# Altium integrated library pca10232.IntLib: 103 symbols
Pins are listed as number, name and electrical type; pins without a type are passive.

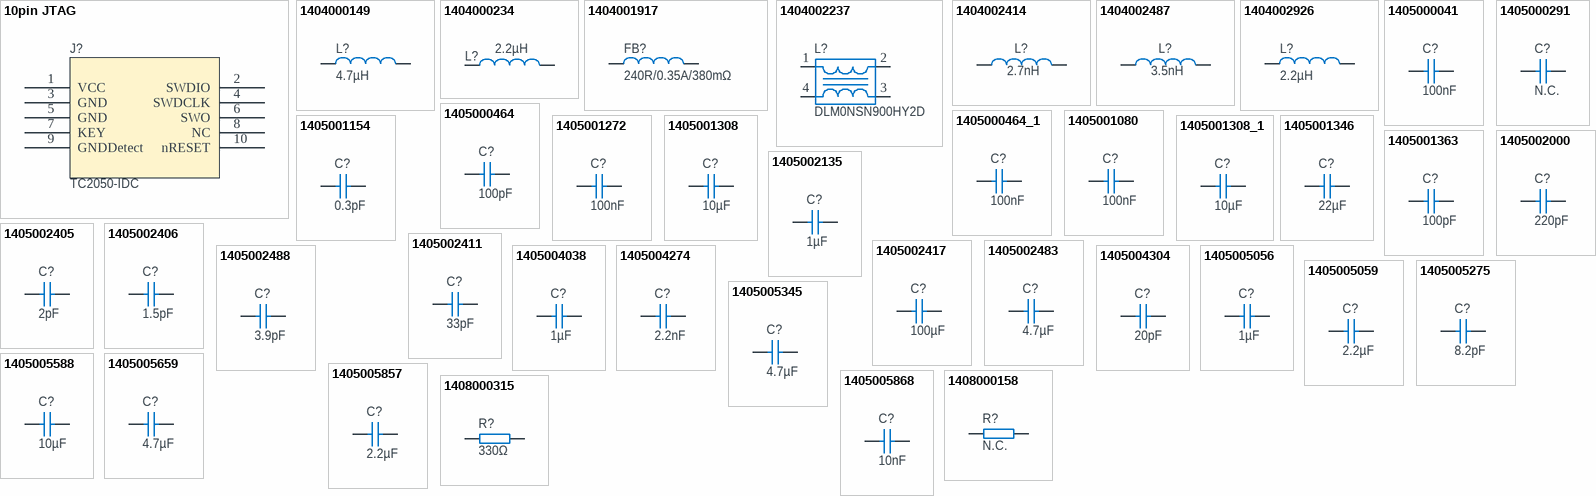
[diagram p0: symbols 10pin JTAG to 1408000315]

## 10pin JTAG
designator J?, comment TC2050-IDC
footprint TC2050-IDC-NLFP
pins: 1 VCC, 2 SWDIO, 3 GND, 4 SWDCLK, 5 GND, 6 SWO, 7 KEY, 8 NC, 9 GNDDetect, 10 nRESET

## 1404000149
designator L?, comment 4.7µH
0603
footprint 0603L_0.6D
footprint 0603C_0.6D(RF)
pins: 1, 2

## 1404000234
designator L?, comment 2.2µH
2.2uH/20%/2.5*2*1.2/2.07A/0.166Ω; Manufacturer Part Number: SWPA252012S2R2MT; Manufacturer: Sunlord
footprint SKFB160808-2R2M
pins: 1, 2

## 1404001917
designator FB?, comment 240R/0.35A/380mΩ
Manufacturer: Murata
footprint 0201_0.25D
footprint 0201L_0.2D(NB)
pins: 1, 2

## 1404002237
designator L?, comment DLM0NSN900HY2D
90Ω/0.1A/3.8Ω; Manufacturer Part Number: DLM0NSM900HY2#; Manufacturer: Murata
footprint L-0.85X0.65
pins: 1 (oe), 2 (oe), 3 (oe), 4 (oe)

## 1404002414
designator L?, comment 2.7nH
2.7nH/±0.1nH/500mA/0.2Ω; Manufacturer Part Number: SDCL0603Q2N7BT02B03; Manufacturer: Sunlord
footprint 0201_0.25D
pins: 1, 2

## 1404002487
designator L?, comment 3.5nH
3.4nH/±0.1nH/450mA/0.25Ω; Manufacturer Part Number: SDCL0603Q3N4BT02B03; Manufacturer: Sunlord
footprint 0201_0.25D
pins: 1, 2

## 1404002926
designator L?, comment 2.2µH
2.2uH/20%/2.0*1.2*0.8/1.7A/146mΩ; Manufacturer Part Number: SKFB201208PA2R2M; Manufacturer: Scientic
footprint 0805L_0.7D-NB
pins: 1, 2

## 1405000041
designator C?, comment 100nF
0.1uF/16V/10%/X7R; Manufacturer Part Number: CC0402KRX7R7BB104; Manufacturer: Yageo
footprint 0402C_0.4D
footprint 0201
footprint 000
footprint 888
pins: 1, 2

## 1405000291
designator C?, comment N.C.
33pF/50V/5%/C0G; Manufacturer Part Number: CC0402JRNPO9BN330; Manufacturer: Yageo
footprint 0402C_0.4D
pins: 1, 2

## 1405000464
designator C?, comment 100pF
100pF/16V/10%/X7R; Manufacturer Part Number: CL05B104KO5NNNC; Manufacturer: Samsung
footprint 0402C_0.4D
pins: 1, 2

## 1405000464_1
designator C?, comment 100nF
0.1uF/16V/10%/X7R; Manufacturer Part Number: CL05B104KO5NNNC; Manufacturer: Samsung
footprint 0402C_0.4D
pins: 1, 2

## 1405001080
designator C?, comment 100nF
0.1uF/10V/10%/X5R; Manufacturer Part Number: 0201X104K100CT; Manufacturer: Walsin
footprint 0201_0.25D
pins: 1, 2

## 1405001154
designator C?, comment 0.3pF
0.3pF/50V/±0.1pF/GQC; Manufacturer Part Number: V0R3B0201GQC500NAT; Manufacturer: Viiyong
footprint 0201_0.25D
pins: 1, 2

## 1405001272
designator C?, comment 100nF
0.1uF/10V/10%/X5R; Manufacturer Part Number: V104K0201X5R100NAT; Manufacturer: Viiyong
footprint 0201_0.25D
pins: 1, 2

## 1405001308
designator C?, comment 10µF
10uF/10V/20%/X5R; Manufacturer Part Number: CL05A106MP5NUNC; Manufacturer: Samsung
footprint 0402C_0.4D
pins: 1, 2

## 1405001308_1
designator C?, comment 10µF
10uF/10V/20%/X5R; Manufacturer Part Number: CL05A106MP5NUNC; Manufacturer: Samsung
footprint 0402C_0.4D
footprint 0402C_0.4D-NB
pins: 1, 2

## 1405001346
designator C?, comment 22µF
22uF/10V/20%/X5R; Manufacturer Part Number: CL10A226MP8NUN#; Manufacturer: Samsung
footprint 0603C_0.6D
pins: 1, 2

## 1405001363
designator C?, comment 100pF
100pF/50V/5%/C0G; Manufacturer Part Number: V101J0201C0G500NAT; Manufacturer: Viiyong
footprint 0201_0.25D
pins: 1, 2

## 1405002000
designator C?, comment 220pF
8pF/50V/0.1pF/C0G; Manufacturer Part Number: GRM0335C1H8R0BA01D; Manufacturer: Murata
footprint 0201_0.25D
footprint 0201C_0.2D(NB)
pins: 1, 2

## 1405002135
designator C?, comment 1µF
1uF/25V/10%/X5R; Manufacturer Part Number: CL05A105KA5NQNC; Manufacturer: Samsung
footprint 0402C_0.4D
pins: 1, 2

## 1405002405
designator C?, comment 2pF
2pF/50V/±0.1pF/GQC; Manufacturer Part Number: V2R0B0201GQC500NAT; Manufacturer: Viiyong
footprint 0201_0.25D
pins: 1, 2

## 1405002406
designator C?, comment 1.5pF
1.5pF/50V/±0.1pF/GQC; Manufacturer Part Number: V1R5B0201GQC500NAT; Manufacturer: Viiyong
footprint 0201_0.25D
pins: 1, 2

## 1405002411
designator C?, comment 33pF
33pF/50V/5%/C0G; Manufacturer Part Number: V330J0201C0G500NAT; Manufacturer: Viiyong
footprint 0201_0.25D
pins: 1, 2

## 1405002417
designator C?, comment 100µF
100uF/6.3V/20%/X5R; Manufacturer Part Number: CL31A107MQHNNNE; Manufacturer: Samsung
footprint 1206C_1.2D
pins: 1, 2

## 1405002483
designator C?, comment 4.7µF
4.7uF/16V/20%/X5R; Manufacturer Part Number: CL05A475MO5NUNC; Manufacturer: Samsung
footprint 0402C_0.4D
pins: 1, 2

## 1405002488
designator C?, comment 3.9pF
3.9pF/50V/±0.1pF/C0G; Manufacturer Part Number: V3R9B0201C0G500NAT; Manufacturer: Viiyong
footprint 0201_0.25D
pins: 1, 2

## 1405004038
designator C?, comment 1µF
1uF/16V/10%/X5R; Manufacturer Part Number: CL05A105KO5NNNC; Manufacturer: Samsung
footprint 0402C_0.4D
pins: 1, 2

## 1405004274
designator C?, comment 2.2nF
2.2nF/16V/10%/X7R; Manufacturer Part Number: CC0201KRX7R7BB222; Manufacturer: Yageo
footprint 0201_0.25D
pins: 1, 2

## 1405004304
designator C?, comment 20pF
20pF/50V/5%/C0G; Manufacturer Part Number: V200J0201C0G500NAT; Manufacturer: Viiyong
footprint 0201_0.25D
pins: 1, 2

## 1405005056
designator C?, comment 1µF
1uF/10V/20%/X5R; Manufacturer Part Number: V105M0201X5R100NXT; Manufacturer: Viiyong
footprint 0201_0.25D
pins: 1, 2

## 1405005059
designator C?, comment 2.2µF
2.2uF/10V/20%/X5R; Manufacturer Part Number: V225M0201X5R100NXT; Manufacturer: Viiyong
footprint 0201_0.25D
pins: 1, 2

## 1405005275
designator C?, comment 8.2pF
8.2pF/50V/±0.1pF/C0G; Manufacturer Part Number: CC0201BRNPO9BN8R2; Manufacturer: Yageo
footprint 0201_0.25D
pins: 1, 2

## 1405005345
designator C?, comment 4.7µF
4.7uF/6.3V/20%/X5R; Manufacturer Part Number: CL03A475MQ5C65C; Manufacturer: Samsung
footprint 0201_0.25D
pins: 1, 2

## 1405005588
designator C?, comment 10µF
10uF/25V/20%/X5R; Manufacturer Part Number: CC0603MRX5R8BB106; Manufacturer: Yageo
footprint 0603C_0.6D
pins: 1, 2

## 1405005659
designator C?, comment 4.7µF
4.7uF/10V/10%/X5R; Manufacturer Part Number: V475K0402X5R100NCT; Manufacturer: Viiyong
footprint 0402C_0.4D
pins: 1, 2

## 1405005857
designator C?, comment 2.2µF
2.2uF/16V/10%/X5R; Manufacturer Part Number: V225K0402X5R160NNT; Manufacturer: Viiyong
footprint 0402C_0.4D
pins: 1, 2

## 1405005868
designator C?, comment 10nF
10nF/25V/10%/X7R; Manufacturer Part Number: V103K0201X7R250NAT; Manufacturer: Viiyong
footprint 0201_0.25D
pins: 1, 2

## 1408000158
designator R?, comment N.C.
10K/5%; Manufacturer Part Number: RC0402JR-0710KL; Manufacturer: Yageo
footprint 0402R_0.4D
pins: 1, 2

## 1408000315
designator R?, comment 330Ω
330Ω/5%; Manufacturer Part Number: 0402WGJ0331TCE; Manufacturer: Uniohm
footprint 0402R_0.4D
pins: 1, 2

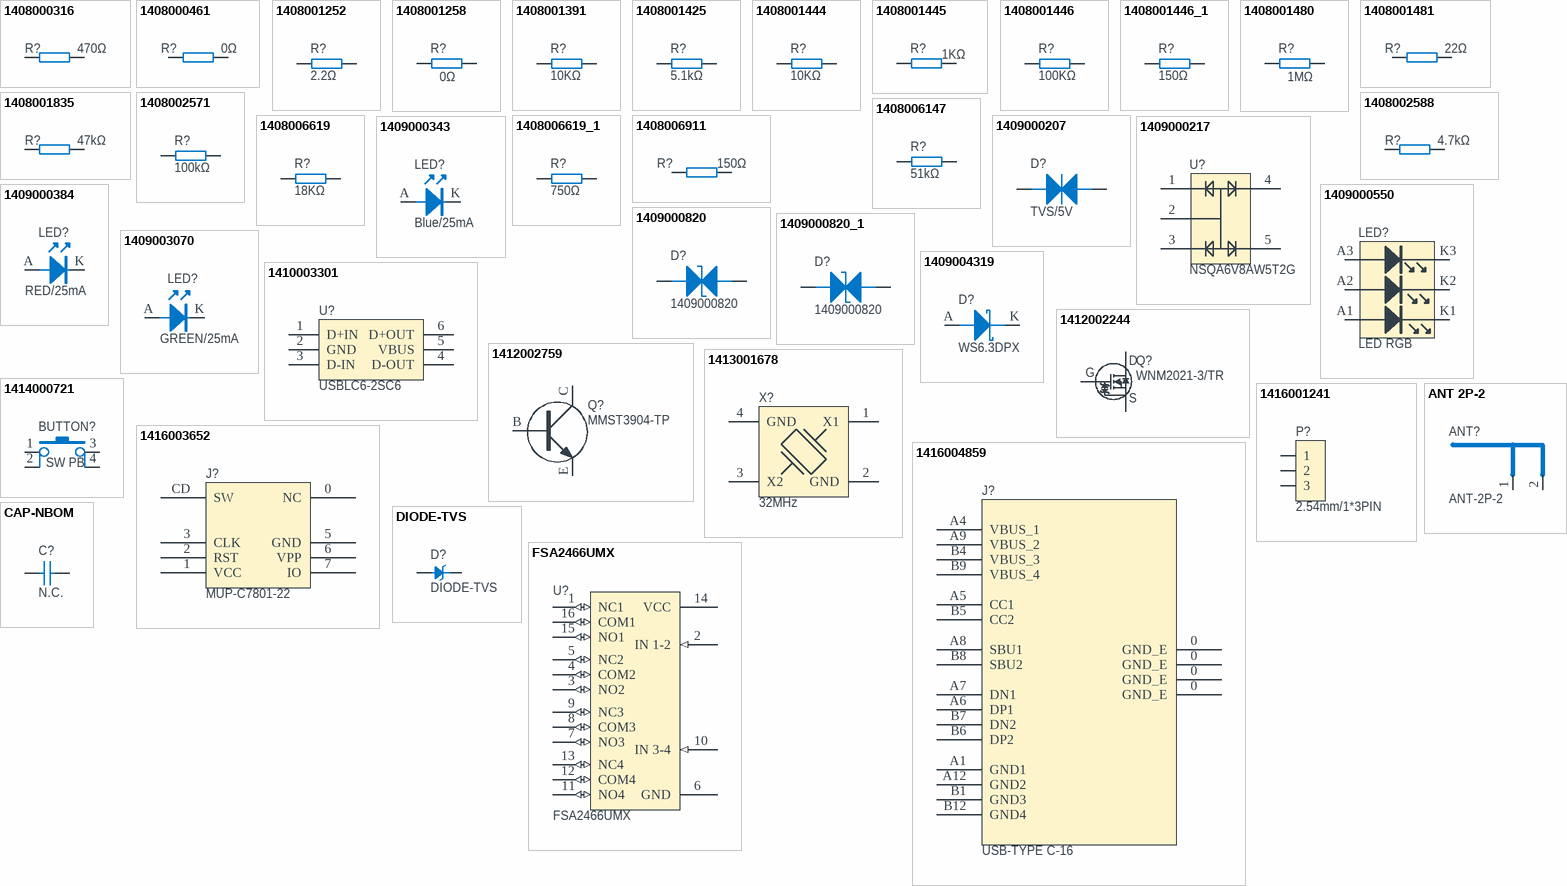
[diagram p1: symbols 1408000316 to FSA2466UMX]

## 1408000316
designator R?, comment 470Ω
470Ω/5%; Manufacturer Part Number: RC0402JR-07470RL; Manufacturer: Yageo
footprint 0402R_0.4D
pins: 1, 2

## 1408000461
designator R?, comment 0Ω
0Ω/5%; Manufacturer Part Number: RC0402JR-070RL; Manufacturer: Yageo
footprint 0402R_0.4D
pins: 1, 2

## 1408001252
designator R?, comment 2.2Ω
2.2Ω/1%; Manufacturer Part Number: 0402WGF220KTCE; Manufacturer: Uniohm
footprint 0402R_0.4D
pins: 1, 2

## 1408001258
designator R?, comment 0Ω
0Ω/1%; Manufacturer Part Number: RC0402FR-070RL; Manufacturer: Yageo
footprint 0402R_0.4D
pins: 1, 2

## 1408001391
designator R?, comment 10KΩ
10KΩ/1%; Manufacturer Part Number: RC0201FR-0710KL; Manufacturer: Yageo
footprint 0201_0.25D
pins: 1, 2

## 1408001425
designator R?, comment 5.1kΩ
5.1KΩ/1%; Manufacturer Part Number: RC0201FR-075K1L; Manufacturer: Yageo
footprint 0201_0.25D
pins: 1, 2

## 1408001444
designator R?, comment 10KΩ
10KΩ/5%; Manufacturer Part Number: RC0201JR-0710KL; Manufacturer: Yageo
footprint 0201_0.25D
pins: 1, 2

## 1408001445
designator R?, comment 1KΩ
1KΩ/5%; Manufacturer Part Number: RC0201JR-071KL; Manufacturer: Yageo
footprint 0201_0.25D
pins: 1, 2

## 1408001446
designator R?, comment 100KΩ
100KΩ/5%; Manufacturer Part Number: RC0201JR-07100KL; Manufacturer: Yageo
footprint 0201_0.25D
pins: 1, 2

## 1408001446_1
designator R?, comment 150Ω
150Ω/5%; Manufacturer: Yageo
footprint 0201_0.25D
pins: 1, 2

## 1408001480
designator R?, comment 1MΩ
1MΩ/1%; Manufacturer Part Number: RC0201FR-071ML; Manufacturer: Yageo
footprint 0201_0.25D
pins: 1, 2

## 1408001481
designator R?, comment 22Ω
22Ω/1%; Manufacturer Part Number: RC0201FR-0722RL; Manufacturer: Yageo
footprint 0201_0.25D
pins: 1, 2

## 1408001835
designator R?, comment 47kΩ
47KΩ/1%; Manufacturer Part Number: RC0201FR-0747KL; Manufacturer: Yageo
footprint 0201_0.25D
pins: 1, 2

## 1408002571
designator R?, comment 100kΩ
100KΩ/1%; Manufacturer Part Number: 0201WMF1003TEE; Manufacturer: Uniohm
footprint 0201_0.25D
pins: 1, 2

## 1408002588
designator R?, comment 4.7kΩ
4.7KΩ/1%; Manufacturer Part Number: 0201WMF4701TEE; Manufacturer: Uniohm
footprint 0201_0.25D
pins: 1, 2

## 1408006147
designator R?, comment 51kΩ
51K/5%; Manufacturer Part Number: RJ0201-51K; Manufacturer: Uniohm
footprint 0201_0.25D
pins: 1, 2

## 1408006619
designator R?, comment 18KΩ
18KΩ/1%; Manufacturer Part Number: RC0201FR-0718KL; Manufacturer: Yageo
footprint 0201_0.25D
pins: 1, 2

## 1408006619_1
designator R?, comment 750Ω
750Ω/1%; Manufacturer: Yageo
footprint 0201_0.25D
pins: 1, 2

## 1408006911
designator R?, comment 150Ω
150Ω/1%; Manufacturer Part Number: RC0201FR-07150RL; Manufacturer: Yageo
footprint 0201_0.25D
pins: 1, 2

## 1409000207
designator D?, comment TVS/5V
ESD; Manufacturer: Nexperia
footprint SOD-523-NP
pins: A, K

## 1409000217
designator U?, comment NSQA6V8AW5T2G
7.14V/600W; Manufacturer: Onsemi
footprint SOT-323-5
pins: 1, 2, 3, 4, 5

## 1409000343
designator LED?, comment Blue/25mA
25mA/28.5-72mcd; Manufacturer Part Number: 16-213/BHC-AN1P2/3T; Manufacturer: Everlight
footprint D0402
pins: A, K

## 1409000384
designator LED?, comment RED/25mA
25mA/40mcd; Manufacturer Part Number: 16-213SURC/S530-A3/TR8; Manufacturer: Everlight
footprint D0402
pins: A, K

## 1409000550
designator LED?, comment LED RGB
25mA/100mcd,180mcd, 50mcd; Manufacturer Part Number: 19-337/R6GHBHC-A01/2T; Manufacturer: Everlight
footprint D1616-RGB
pins: A1 A, A2 A, A3 A, K1 K, K2 K, K3 K

## 1409000820
designator D?
5V/100W
footprint D0201-NP
pins: A, K

## 1409000820_1
designator D?, comment 1409000820
5V/100W
footprint DFN1006
pins: A, K

## 1409003070
designator LED?, comment GREEN/25mA
25mA/112-225mcd; Manufacturer Part Number: 16-213/GHC-YR1S1N/3T; Manufacturer: Everlight
footprint D0402
pins: A, K

## 1409004319
designator D?, comment WS6.3DPX
Manufacturer: Walsin
footprint UDFN2(1610)
pins: A, K

## 1410003301
designator U?, comment USBLC6-2SC6
USB; Manufacturer: ST
footprint SOT-23-6P
pins: 1 D+IN, 2 GND, 3 D-IN, 4 D-OUT, 5 VBUS, 6 D+OUT

## 1412002244
designator Q?, comment WNM2021-3/TR
NMOS/20V/0.89A; Manufacturer: Willsemi
footprint SOT-323-3G
pins: D, G, S

## 1412002759
designator Q?, comment MMST3904-TP
NPN/200mA/40V/200mW; Manufacturer: MCC
footprint SOT-323-3A
pins: B 1, C 3, E 2

## 1413001678
designator X?, comment 32MHz
8pF/32MHz/10PPM/-40~85℃; Manufacturer Part Number: 9S32000073
footprint 2016
pins: 1 X1, 2 GND, 3 X2, 4 GND

## 1414000721
designator BUTTON?, comment SW PB
3.2*4.2*2.5mm; Manufacturer Part Number: BL-QC-3.2X4.2
footprint SW-4.2X3.35-4P-S
pins: 1, 2, 3, 4

## 1416001241
designator P?, comment 2.54mm/1*3PIN
Manufacturer Part Number: CNT-M254-1*3-GS-6/3-01
footprint SIP 2.54_3_S
pins: 1, 2, 3

## 1416003652
designator J?, comment MUP-C7801-22
NANO SIM; Manufacturer: MUP
footprint SIM-MUP-C7801
pins: 0 NC, 1 VCC, 2 RST, 3 CLK, 5 GND, 6 VPP, 7 IO, CD SW

## 1416004859
designator J?, comment USB-TYPE C-16
USB2.0 TpyeC; Manufacturer Part Number: MUP-U20402-01; Manufacturer: MUP
footprint USB-TYPEC-MUP-U20402-1
pins: 0 GND_E, 0 GND_E, 0 GND_E, 0 GND_E, A1 GND1, A4 VBUS_1, A5 CC1, A6 DP1, A7 DN1, A8 SBU1, A9 VBUS_2, A12 GND2, B1 GND3, B4 VBUS_3, B5 CC2, B6 DP2, B7 DN2, B8 SBU2, B9 VBUS_4, B12 GND4

## ANT 2P-2
designator ANT?, comment ANT-2P-2  (no BOM)
ANT
footprint ANT_PCB
pins: 1 "-1", 2 "-1"

## CAP-NBOM
designator C?, comment N.C.
Manufacturer Part Number: N.A.
footprint 0402C_0.4D
footprint 0603C_0.6D
footprint 0805C_0.6D
footprint 0201_0.25D
footprint 1206C_1.2D
footprint CY-L7W3P5
footprint CY-L9W3_5P7_5
footprint CY-L10W3_5P8
footprint CY-L11W5P7_5
footprint CY-L15W3_5P10
footprint CX-L10_5W4P7_5
footprint CX-L10_5W5P7_5
footprint CX-L10_5W6P7_5
footprint CX-L13W4P10
footprint CX-L13W5P10
footprint CX-L13W6P10
footprint CX-L13W7P10
footprint CX-L13W8P10
footprint CX-L17_5W5P15
footprint CX-L17_5W6P15
footprint CX-L17_5W10P15
footprint CX-L17.5W8P15
footprint CX-L26_5W6P22_5
footprint 01005_0.16D
pins: 1, 2

## DIODE-TVS
designator D?
4.5V; Manufacturer Part Number: WS4.5DPVL; Manufacturer: Walsin
footprint UDFN2(1610) (Footprint not found)
footprint UDFN2(1610)
pins: A, K

## FSA2466UMX
designator U?
Data / Audio Low-Voltage Dual DPDT Analog Switch; Manufacturer: Onsemi
footprint FSA2466UMX_1.8x2.6_0.4
pins: 1 NC1 (io), 2 IN 1-2 (in), 3 NO2 (io), 4 COM2 (io), 5 NC2 (io), 6 GND (power), 7 NO3 (io), 8 COM3 (io), 9 NC3 (io), 10 IN 3-4 (in), 11 NO4 (io), 12 COM4 (io), 13 NC4 (io), 14 VCC (power), 15 NO1 (io), 16 COM1 (io)
1 alternate drawing of the same symbol

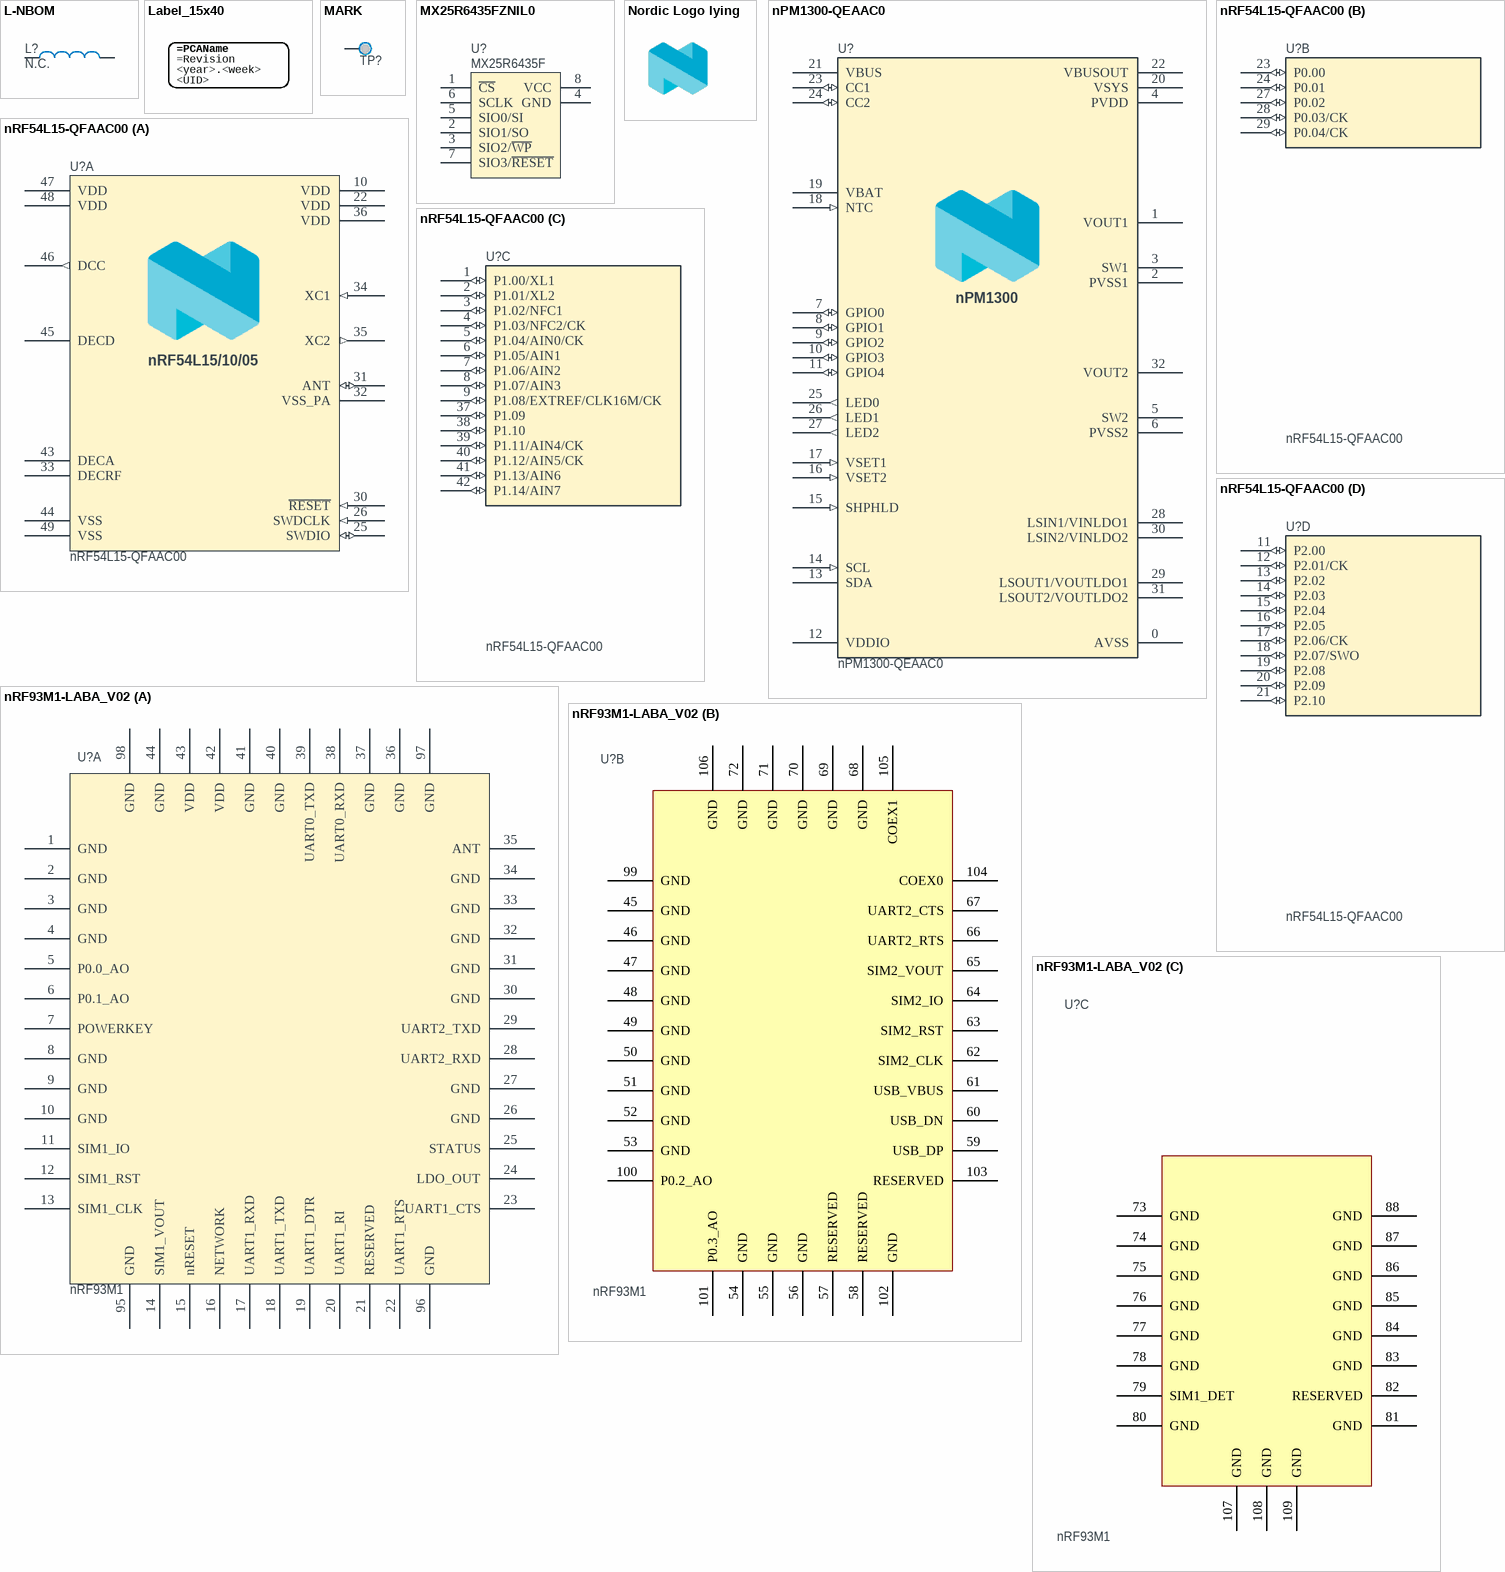
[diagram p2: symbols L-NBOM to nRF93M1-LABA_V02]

## L-NBOM
designator L?, comment N.C.
Manufacturer Part Number: N.A.
footprint 0201_0.25D
footprint 0402L_0.4D
footprint 0603L_0.6D
footprint 0805L_0.6D
footprint 2520-L
footprint 1206L_1.8D
footprint 3X3-L
footprint 4X4-L
footprint 5X5-L
footprint 6X6-L
footprint 8X8-L
footprint 01005_0.16D
pins: 1, 2

## Label_15x40
designator LABEL?, comment Solderbridge  (value not drawn)  (graphical)
PCA version label, stick-on, 15x40mm
footprint LabelSilk_15x40

## MARK
designator TP?, comment Testpoint  (value not drawn)  (no BOM)
Manufacturer Part Number: N.A.
footprint test
footprint Bad Mark
pins: 1

## MX25R6435FZNIL0
designator U?, comment MX25R6435F
Ultra low power, 64M-bit, serial multi I/O flash memory; Manufacturer: Macronix
footprint WSON8L_6X5_1.27
pins: 1 ~{CS}, 2 SIO1/SO, 3 SIO2/~{WP}, 4 GND, 5 SIO0/SI, 6 SCLK, 7 SIO3/~{RESET}, 8 VCC, 9 GND hidden to GND

## Nordic Logo lying
designator LOGO?, comment Solderbridge  (value not drawn)  (graphical)
Nordic logo lying
footprint NORDIC_LOGO_LYING

## nPM1300-QEAAC0
designator U?
Li-Ion/Li-Polymer USB-C battery charger with high efficiency buck regulators, LDOs or load switches, LED drivers, TWI and VBUSOUT; Manufacturer: Nordic Semiconductor
footprint QFN32(0.5)-5X5
pins: 0 AVSS (power), 1 VOUT1 (power), 2 PVSS1 (power), 3 SW1 (power), 4 PVDD (power), 5 SW2 (power), 6 PVSS2 (power), 7 GPIO0 (io), 8 GPIO1 (io), 9 GPIO2 (io), 10 GPIO3 (io), 11 GPIO4 (io), 12 VDDIO (power), 13 SDA (oc), 14 SCL (in), 15 SHPHLD (in), 16 VSET2 (in), 17 VSET1 (in), 18 NTC (in), 19 VBAT, 20 VSYS (power), 21 VBUS (power), 22 VBUSOUT (power), 23 CC1 (io), 24 CC2 (io), 25 LED0 (out), 26 LED1 (out), 27 LED2 (out), 28 LSIN1/VINLDO1 (power), 29 LSOUT1/VOUTLDO1 (power), 30 LSIN2/VINLDO2 (power), 31 LSOUT2/VOUTLDO2 (power), 32 VOUT2 (power)

## nRF54L15-QFAAC00
designator U?
Multi-protocol Bluetooth Low Energy, IEEE 802.15.4 and 2.4GHz proprietary Wireless MCU; Manufacturer: Nordic Semiconductor
footprint nRF54L15_QFN48_6X6_0.4
part A pins: 10 VDD (power), 22 VDD (power), 25 SWDIO (io), 26 SWDCLK (in), 30 ~{RESET} (in), 31 ANT (io), 32 VSS_PA (power), 33 DECRF (power), 34 XC1 (in), 35 XC2 (out), 36 VDD (power), 43 DECA (power), 44 VSS (power), 45 DECD (power), 46 DCC (out), 47 VDD (power), 48 VDD (power), 49 VSS (power)
part B pins: 23 P0.00 (io), 24 P0.01 (io), 27 P0.02 (io), 28 P0.03/CK (io), 29 P0.04/CK (io)
part C pins: 1 P1.00/XL1 (io), 2 P1.01/XL2 (io), 3 P1.02/NFC1 (io), 4 P1.03/NFC2/CK (io), 5 P1.04/AIN0/CK (io), 6 P1.05/AIN1 (io), 7 P1.06/AIN2 (io), 8 P1.07/AIN3 (io), 9 P1.08/EXTREF/CLK16M/CK (io), 37 P1.09 (io), 38 P1.10 (io), 39 P1.11/AIN4/CK (io), 40 P1.12/AIN5/CK (io), 41 P1.13/AIN6 (io), 42 P1.14/AIN7 (io)
part D pins: 11 P2.00 (io), 12 P2.01/CK (io), 13 P2.02 (io), 14 P2.03 (io), 15 P2.04 (io), 16 P2.05 (io), 17 P2.06/CK (io), 18 P2.07/SWO (io), 19 P2.08 (io), 20 P2.09 (io), 21 P2.10 (io)

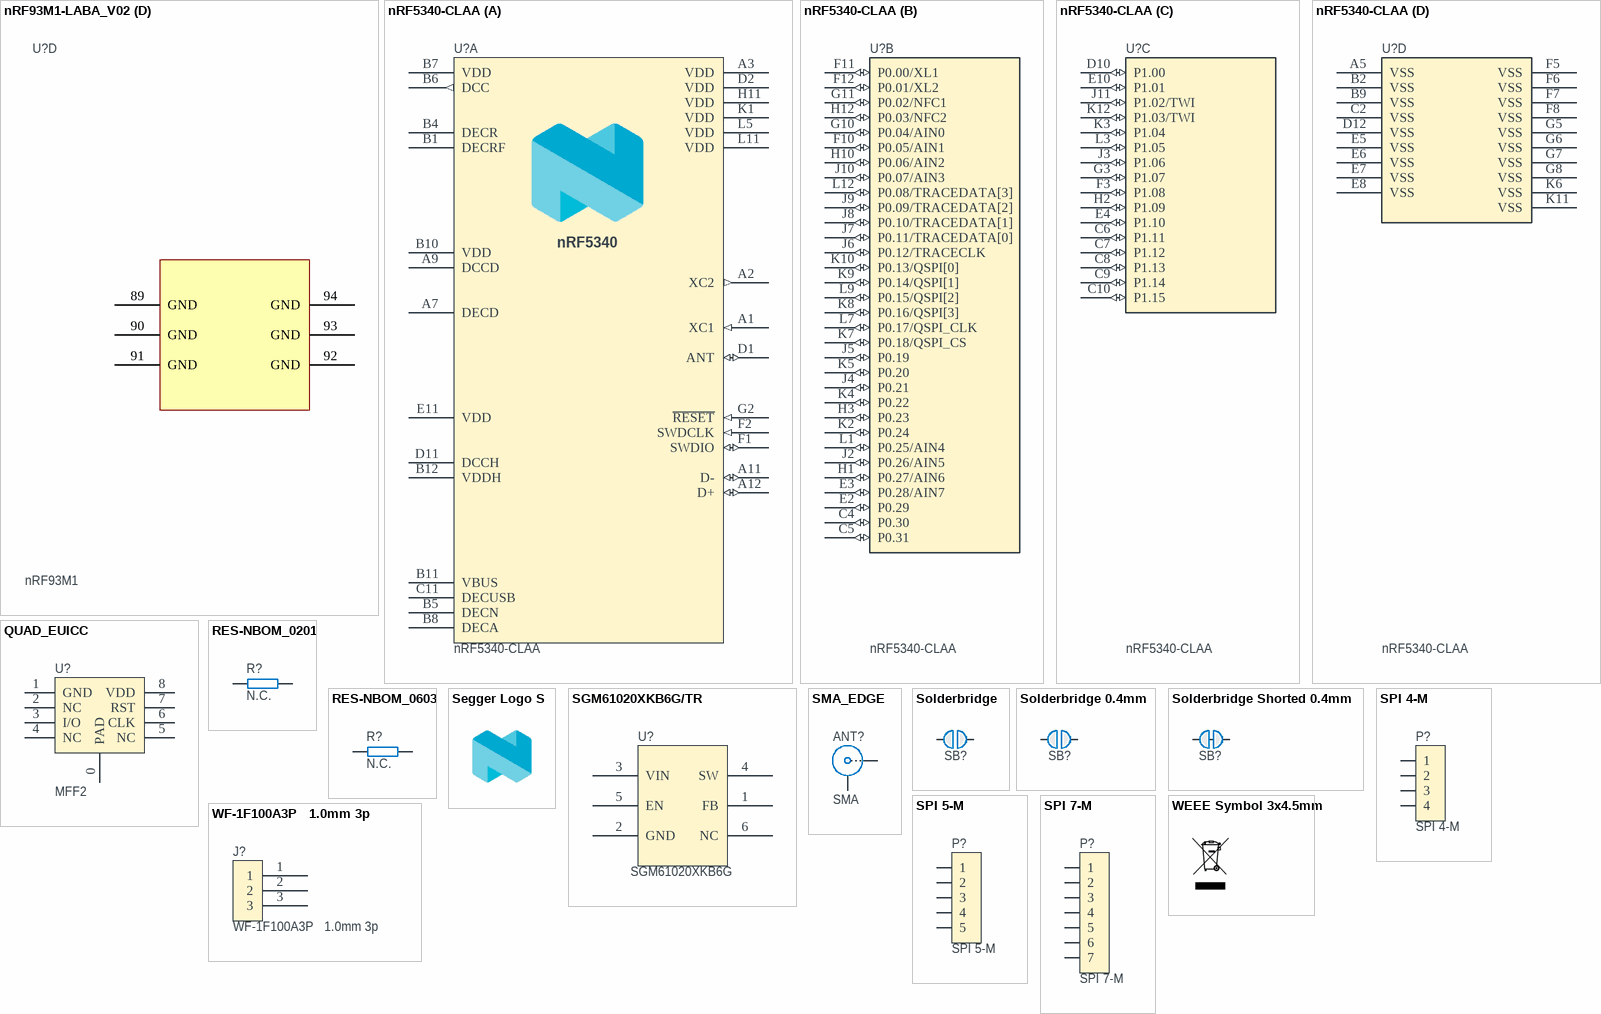
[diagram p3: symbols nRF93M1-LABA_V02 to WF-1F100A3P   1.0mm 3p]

## nRF93M1-LABA_V02
designator U?, comment nRF93M1
Manufacturer: Nordic Semiconductor
footprint nRF93M1
part A pins: 1 GND, 2 GND, 3 GND, 4 GND, 5 P0.0_AO, 6 P0.1_AO, 7 POWERKEY, 8 GND, 9 GND, 10 GND, 11 SIM1_IO, 12 SIM1_RST, 13 SIM1_CLK, 14 SIM1_VOUT, 15 nRESET, 16 NETWORK, 17 UART1_RXD, 18 UART1_TXD, 19 UART1_DTR, 20 UART1_RI, 21 RESERVED, 22 UART1_RTS, 23 UART1_CTS, 24 LDO_OUT, 25 STATUS, 26 GND, 27 GND, 28 UART2_RXD, 29 UART2_TXD, 30 GND, 31 GND, 32 GND, 33 GND, 34 GND, 35 ANT, 36 GND, 37 GND, 38 UART0_RXD, 39 UART0_TXD, 40 GND, 41 GND, 42 VDD, 43 VDD, 44 GND, 95 GND, 96 GND, 97 GND, 98 GND
part B pins: 45 GND, 46 GND, 47 GND, 48 GND, 49 GND, 50 GND, 51 GND, 52 GND, 53 GND, 54 GND, 55 GND, 56 GND, 57 RESERVED, 58 RESERVED, 59 USB_DP, 60 USB_DN, 61 USB_VBUS, 62 SIM2_CLK, 63 SIM2_RST, 64 SIM2_IO, 65 SIM2_VOUT, 66 UART2_RTS, 67 UART2_CTS, 68 GND, 69 GND, 70 GND, 71 GND, 72 GND, 99 GND, 100 P0.2_AO, 101 P0.3_AO, 102 GND, 103 RESERVED, 104 COEX0, 105 COEX1, 106 GND
part C pins: 73 GND, 74 GND, 75 GND, 76 GND, 77 GND, 78 GND, 79 SIM1_DET, 80 GND, 81 GND, 82 RESERVED, 83 GND, 84 GND, 85 GND, 86 GND, 87 GND, 88 GND, 107 GND, 108 GND, 109 GND
part D pins: 89 GND, 90 GND, 91 GND, 92 GND, 93 GND, 94 GND

## nRF5340-CLAA
designator U?
Multi-protocol Bluetooth Low Energy, IEEE 802.15.4, ANT and 2.4GHz proprietary system-on-chip; Manufacturer: Nordic Semiconductor
footprint BGA95C35P12X11_437X397X50
part A pins: A1 XC1 (in), A2 XC2 (out), A3 VDD (power), A7 DECD (power), A9 DCCD (power), A11 D- (io), A12 D+ (io), B1 DECRF (power), B4 DECR (power), B5 DECN (power), B6 DCC (out), B7 VDD (power), B8 DECA (power), B10 VDD (power), B11 VBUS (power), B12 VDDH (power), C11 DECUSB (power), D1 ANT (io), D2 VDD (power), D11 DCCH (power), E11 VDD (power), F1 SWDIO (io), F2 SWDCLK (in), G2 ~{RESET} (in), H11 VDD (power), K1 VDD (power), L5 VDD (power), L11 VDD (power)
part B pins: C4 P0.30 (io), C5 P0.31 (io), E2 P0.29 (io), E3 P0.28/AIN7 (io), F10 P0.05/AIN1 (io), F11 P0.00/XL1 (io), F12 P0.01/XL2 (io), G10 P0.04/AIN0 (io), G11 P0.02/NFC1 (io), H1 P0.27/AIN6 (io), H3 P0.23 (io), H10 P0.06/AIN2 (io), H12 P0.03/NFC2 (io), J2 P0.26/AIN5 (io), J4 P0.21 (io), J5 P0.19 (io), J6 P0.12/TRACECLK (io), J7 P0.11/TRACEDATA[0] (io), J8 P0.10/TRACEDATA[1] (io), J9 P0.09/TRACEDATA[2] (io), J10 P0.07/AIN3 (io), K2 P0.24 (io), K4 P0.22 (io), K5 P0.20 (io), K7 P0.18/QSPI_CS (io), K8 P0.16/QSPI[3] (io), K9 P0.14/QSPI[1] (io), K10 P0.13/QSPI[0] (io), L1 P0.25/AIN4 (io), L7 P0.17/QSPI_CLK (io), L9 P0.15/QSPI[2] (io), L12 P0.08/TRACEDATA[3] (io)
part C pins: C6 P1.11 (io), C7 P1.12 (io), C8 P1.13 (io), C9 P1.14 (io), C10 P1.15 (io), D10 P1.00 (io), E4 P1.10 (io), E10 P1.01 (io), F3 P1.08 (io), G3 P1.07 (io), H2 P1.09 (io), J3 P1.06 (io), J11 P1.02/TWI (io), K3 P1.04 (io), K12 P1.03/TWI (io), L3 P1.05 (io)
part D pins: A5 VSS (power), B2 VSS (power), B9 VSS (power), C2 VSS (power), D12 VSS (power), E5 VSS (power), E6 VSS (power), E7 VSS (power), E8 VSS (power), F5 VSS (power), F6 VSS (power), F7 VSS (power), F8 VSS (power), G5 VSS (power), G6 VSS (power), G7 VSS (power), G8 VSS (power), K6 VSS (power), K11 VSS (power)

## QUAD_EUICC
designator U?, comment MFF2
footprint MFF2
pins: 0 PAD, 1 GND, 2 NC, 3 I/O, 4 NC, 5 NC, 6 CLK, 7 RST, 8 VDD

## RES-NBOM_0201
designator R?, comment N.C.
Manufacturer Part Number: N.A.
footprint 0201_0.25D
pins: 1, 2

## RES-NBOM_0603
designator R?, comment N.C.
Manufacturer Part Number: N.A.
footprint 0603R_0.6D
pins: 1, 2

## Segger Logo S
designator LOGO?  (value not drawn)  (no BOM)
Segger logo, small size; Manufacturer: N.A.
footprint logo (Footprint not found)

## SGM61020XKB6G/TR
designator U?, comment SGM61020XKB6G
Manufacturer Part Number: SGM61020XKB6G/TR; Manufacturer: SG Micro
footprint SOT-563-6
pins: 1 FB, 2 GND, 3 VIN, 4 SW, 5 EN, 6 NC

## SMA_EDGE
designator ANT?, comment SMA
CON SMA RCPT STR 50OHM EDGE MNT; Manufacturer: SMA edge
footprint 0732511150_ALT
footprint SMA-SMD
pins: 1 X, 2 Y

## Solderbridge
designator SB?  (value not drawn)  (no BOM)
Manufacturer: N.A.
footprint Solderbridge
footprint Solderbridge_NO_Shorted
pins: 1 0, 2 1

## Solderbridge 0.4mm
designator SB?, comment Solderbridge  (value not drawn)  (no BOM)
Manufacturer: N.A.
footprint Solderbridge_NO_Shorted
pins: 1 0, 2 1

## Solderbridge Shorted 0.4mm
designator SB?, comment Solderbridge_Shorted  (value not drawn)  (net tie, no BOM)
Shorted Solderbridge; Manufacturer: N.A.
footprint Solderbridge_Shorted
pins: 1 0, 2 1

## SPI 4-M
designator P?
footprint SIP 2.54_4_S
pins: 1, 2, 3, 4

## SPI 5-M
designator P?
footprint SIP 2.54_5_S
pins: 1, 2, 3, 4, 5

## SPI 7-M
designator P?
footprint SIP 2.54_7_S
pins: 1, 2, 3, 4, 5, 6, 7

## WEEE Symbol 3x4.5mm
designator LOGO?, comment WEE Symbol  (value not drawn)  (no BOM)
WEEE Directive symbol; Manufacturer: N.A.
footprint WEEE_3x4.5mm

## WF-1F100A3P   1.0mm 3p
designator J?
footprint CON1
pins: 1, 2, 3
